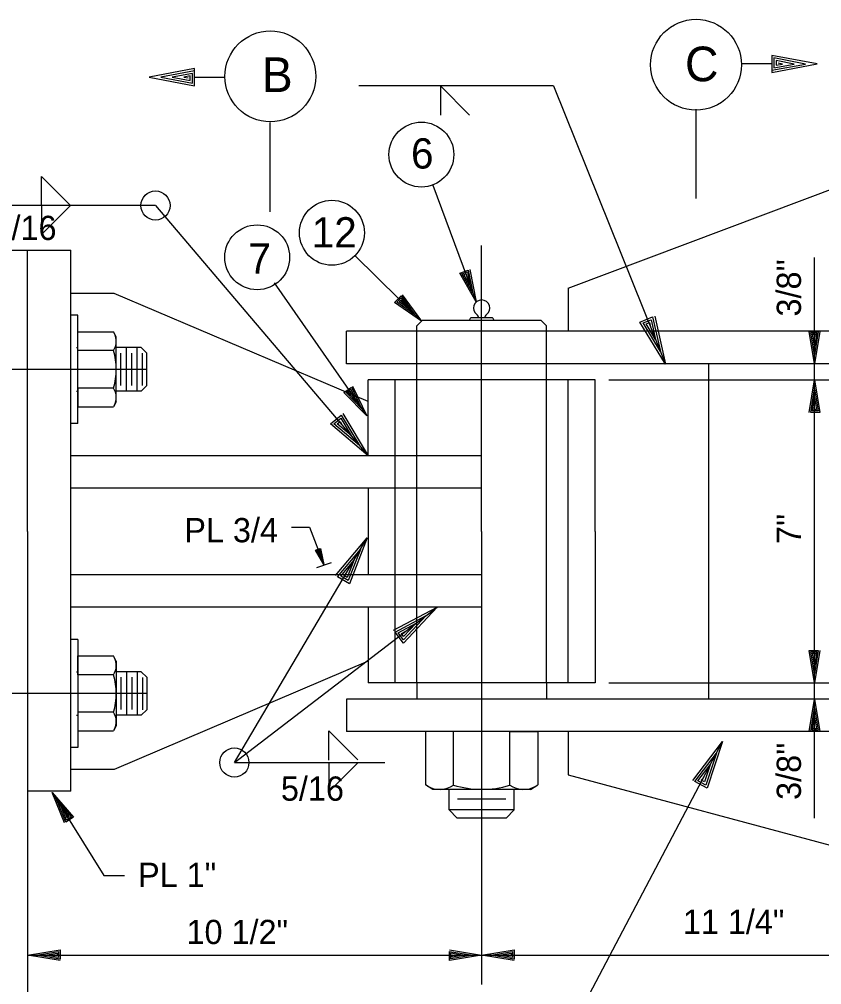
# Model space of a CAD drawing. Extents: x 0.1 to 13.5, y 0.1 to 9.5.
# Drawn here: x 2.665 to 4.211, y 1.527 to 3.386 of the extents above; entities that cross this region are included whole.
import ezdxf

# ---------------------------------------------------------------- set-up
doc = ezdxf.new("R2010")
doc.units = 0
for name, color, linetype in [('Level 2', 7, 'Continuous'), ('Level 25', 7, 'Continuous'), ('Level 3', 7, 'Continuous'), ('Level 4', 7, 'Continuous'), ('Level 50', 7, 'Continuous')]:
    doc.layers.add(name, color=color, linetype=linetype)

msp = doc.modelspace()

# ---------------------------------------------------------------- linework, layer by layer
at = {"layer": 'Level 2'}
for p, q in [((2.681, 2.3997), (2.681, 2.9413)), ((2.7644, 1.8997), (2.7644, 2.9413)), ((3.556, 2.3997), (3.556, 2.9502)), ((3.7227, 2.8684), (3.7227, 2.7851)), ((2.8477, 2.858), (2.7644, 2.858)), ((2.7777, 2.8159), (2.7646, 2.8159)), ((2.7777, 2.6076), (2.7777, 2.8159)), ((3.575, 2.8111), (3.537, 2.8111)), ((3.556, 2.8111), (3.556, 2.8111)), ((3.556, 2.8111), (3.556, 2.8111)), ((3.4415, 2.8059), (3.431, 2.7955)), ((3.431, 2.7851), (3.431, 2.7955)), ((3.6706, 2.8059), (3.4415, 2.8059)), ((3.5329, 2.8059), (3.5329, 2.8069)), ((3.5791, 2.8059), (3.5791, 2.8069)), ((3.6706, 2.8059), (3.681, 2.7955)), ((3.681, 2.7851), (3.681, 2.7955)), ((2.7777, 2.784), (2.8462, 2.784)), ((2.8518, 2.7743), (2.8462, 2.784)), ((2.8518, 2.6492), (2.8518, 2.7743)), ((4.306, 2.7851), (3.2956, 2.7851)), ((3.2956, 2.7226), (3.2956, 2.7851)), ((3.431, 2.7226), (3.431, 2.7851)), ((3.681, 2.7226), (3.681, 2.7851)), ((2.775, 2.7536), (2.7777, 2.7536)), ((2.9, 2.7536), (2.8518, 2.7536)), ((2.8714, 2.6699), (2.8714, 2.7536)), ((2.8923, 2.6699), (2.8923, 2.7536)), ((2.9, 2.7536), (2.9105, 2.7431)), ((2.8464, 2.7479), (2.7777, 2.7479)), ((2.8609, 2.6805), (2.8609, 2.7427)), ((2.8818, 2.6805), (2.8818, 2.7427)), ((2.9023, 2.681), (2.9023, 2.7432)), ((2.9105, 2.6804), (2.9105, 2.7431)), ((2.9105, 2.6804), (2.9105, 2.7431)), ((4.306, 2.7226), (3.2956, 2.7226)), ((3.431, 2.6913), (3.431, 2.7226)), ((3.681, 2.6913), (3.681, 2.7226)), ((3.9935, 2.0768), (3.9935, 2.7226)), ((2.9, 2.6699), (2.9105, 2.6804)), ((3.7748, 2.6913), (3.3373, 2.6913)), ((3.3373, 2.5455), (3.3373, 2.6913)), ((3.3894, 2.108), (3.3894, 2.6913)), ((3.431, 2.108), (3.431, 2.6913)), ((3.681, 2.108), (3.681, 2.6913)), ((3.7227, 2.108), (3.7227, 2.6913)), ((3.7748, 2.3997), (3.7748, 2.6913)), ((2.775, 2.6699), (2.7777, 2.6699)), ((2.7777, 2.6761), (2.7777, 2.6395)), ((2.8464, 2.6756), (2.7777, 2.6756)), ((2.9, 2.6699), (2.8518, 2.6699)), ((2.8518, 2.6492), (2.8462, 2.6395)), ((2.7777, 2.6395), (2.8462, 2.6395)), ((2.7777, 2.6076), (2.7646, 2.6076)), ((3.556, 2.5455), (2.7644, 2.5455)), ((3.556, 2.483), (3.556, 2.5455)), ((3.556, 2.483), (2.7644, 2.483)), ((3.3373, 2.483), (3.3373, 2.3163)), ((2.681, 2.3997), (2.681, 1.4864)), ((3.556, 2.3997), (3.556, 1.5274)), ((3.7748, 2.3997), (3.7748, 2.108)), ((3.556, 2.3163), (2.7644, 2.3163)), ((3.556, 2.3163), (3.556, 2.2538)), ((3.556, 2.2538), (2.7644, 2.2538)), ((3.3373, 2.2538), (3.3373, 2.108)), ((2.7777, 2.1917), (2.7646, 2.1917)), ((2.7777, 2.1917), (2.7777, 1.9834)), ((2.7777, 2.1232), (2.7777, 2.1598)), ((2.7777, 2.1598), (2.8462, 2.1598)), ((2.8518, 2.1501), (2.8462, 2.1598)), ((2.8518, 2.1501), (2.8518, 2.025)), ((2.775, 2.1294), (2.7777, 2.1294)), ((2.8464, 2.1238), (2.7777, 2.1238)), ((2.9, 2.1294), (2.8518, 2.1294)), ((2.8714, 2.1294), (2.8714, 2.0457)), ((2.8923, 2.1294), (2.8923, 2.0457)), ((2.9, 2.1294), (2.9105, 2.1189)), ((2.8609, 2.1188), (2.8609, 2.0566)), ((2.8818, 2.1188), (2.8818, 2.0566)), ((2.9023, 2.1183), (2.9023, 2.0561)), ((2.9105, 2.1189), (2.9105, 2.0562)), ((2.9105, 2.1189), (2.9105, 2.0562)), ((3.7748, 2.108), (3.3373, 2.108)), ((3.431, 2.108), (3.431, 2.0768)), ((3.681, 2.108), (3.681, 2.0768)), ((4.306, 2.0768), (3.2956, 2.0768)), ((3.2956, 2.0768), (3.2956, 2.0143)), ((2.775, 2.0457), (2.7777, 2.0457)), ((2.8464, 2.0514), (2.7777, 2.0514)), ((2.9, 2.0457), (2.8518, 2.0457)), ((2.9, 2.0457), (2.9105, 2.0562)), ((2.7777, 2.0154), (2.8462, 2.0154)), ((2.8518, 2.025), (2.8462, 2.0154)), ((4.306, 2.0143), (3.2956, 2.0143)), ((3.7123, 2.0143), (3.3998, 2.0143)), ((3.4477, 2.0143), (3.4477, 1.9114)), ((3.5018, 1.9112), (3.5018, 2.0143)), ((3.6095, 2.0143), (3.6644, 2.0143)), ((3.6103, 1.9112), (3.6103, 2.0143)), ((3.6644, 2.0143), (3.6644, 1.9114)), ((3.7227, 2.0143), (3.7227, 1.9309)), ((2.7777, 1.9834), (2.7646, 1.9834)), ((2.8477, 1.9413), (2.7644, 1.9413)), ((2.7644, 1.8997), (2.681, 1.8997)), ((3.4622, 1.903), (3.4477, 1.9114)), ((3.6499, 1.903), (3.4622, 1.903)), ((3.4933, 1.8633), (3.4933, 1.903)), ((3.6188, 1.8633), (3.6188, 1.903)), ((3.6499, 1.903), (3.6644, 1.9114)), ((3.6029, 1.8843), (3.5096, 1.8843)), ((3.4933, 1.8633), (3.509, 1.8476)), ((3.6188, 1.8633), (3.4933, 1.8633)), ((3.6188, 1.8633), (3.6031, 1.8476)), ((3.6031, 1.8476), (3.509, 1.8476)), ((3.6031, 1.8476), (3.509, 1.8476)), ((3.6029, 1.8476), (3.5096, 1.8476))]:
    msp.add_line(p, q, dxfattribs=at)
for centre, radius, start, end in [((3.556, 2.8298), 0.0156, 306.8699, 233.1301), ((3.537, 2.8069), 0.00417, 90, 180), ((3.5404, 2.8089), 0.0104, 11.771, 53.1301), ((3.5717, 2.8089), 0.0104, 126.8699, 168.229), ((3.575, 2.8069), 0.00417, 0, 90), ((2.8205, 2.7657), 0.0314, 325.489, 30.2876), ((2.7264, 2.7113), 0.1255, 343.5034, 16.9816), ((2.8205, 2.6578), 0.0314, 329.7124, 34.511), ((2.8205, 2.1415), 0.0314, 325.489, 30.2876), ((2.7264, 2.088), 0.1255, 343.0184, 16.4966), ((2.8205, 2.0336), 0.0314, 329.7124, 34.511), ((3.4751, 1.9499), 0.047, 239.7124, 304.511), ((3.5567, 2.0912), 0.1882, 253.0184, 286.4966), ((3.6369, 1.9499), 0.047, 235.489, 300.2876)]:
    msp.add_arc(centre, radius, start, end, dxfattribs=at)
at = {"layer": 'Level 25'}
for p, q in [((3.7227, 2.8684), (4.306, 3.0872)), ((2.5977, 2.9413), (2.681, 2.9413)), ((2.681, 2.9413), (2.7644, 2.9413)), ((3.3373, 2.6497), (2.8477, 2.858)), ((3.9004, 2.7461), (3.9004, 2.7461)), ((3.9101, 2.7219), (3.9101, 2.7219)), ((2.7644, 2.6497), (2.7644, 2.6497)), ((3.3204, 2.5653), (3.3204, 2.5653)), ((3.3373, 2.5455), (3.3373, 2.5455)), ((3.3355, 2.3873), (3.3355, 2.3873)), ((3.3222, 2.3649), (3.3222, 2.3649)), ((3.0794, 1.9546), (3.47, 2.2538)), ((3.47, 2.2538), (3.47, 2.2538)), ((3.4493, 2.238), (3.4493, 2.238)), ((3.3373, 2.1497), (2.8477, 1.9413)), ((3.7141, 1.4148), (4.0204, 1.9954)), ((4.0204, 1.9954), (4.0204, 1.9954)), ((4.0083, 1.9724), (4.0083, 1.9724)), ((3.7227, 1.9309), (4.306, 1.7747))]:
    msp.add_line(p, q, dxfattribs=at)
for points in [[(3.8896, 2.8145), (3.9101, 2.7219), (3.8608, 2.8029), (3.8854, 2.8128), (3.9004, 2.7461), (3.867, 2.8011), (3.8828, 2.8074), (3.8911, 2.7693), (3.8731, 2.7992), (3.8796, 2.8018), (3.8814, 2.7934)], [(3.2885, 2.6268), (3.3373, 2.5455), (3.2649, 2.6067), (3.2851, 2.6238), (3.3204, 2.5653), (3.2713, 2.6069), (3.2843, 2.6179), (3.3042, 2.5843), (3.2777, 2.6071), (3.283, 2.6116), (3.2874, 2.6041)], [(3.2745, 2.3148), (3.3355, 2.3873), (3.3012, 2.299), (3.2784, 2.3125), (3.3222, 2.3649), (3.2989, 2.305), (3.2843, 2.3136), (3.3095, 2.3434), (3.2966, 2.3109), (3.2906, 2.3145), (3.2962, 2.3211)], [(3.3863, 2.2093), (3.47, 2.2538), (3.4052, 2.1847), (3.3891, 2.2057), (3.4493, 2.238), (3.4053, 2.1911), (3.395, 2.2046), (3.4295, 2.2228), (3.4055, 2.1975), (3.4012, 2.203), (3.4089, 2.207)], [(3.9631, 1.9199), (4.0204, 1.9954), (3.9905, 1.9054), (3.967, 1.9178), (4.0083, 1.9724), (3.9879, 1.9113), (3.9729, 1.9193), (3.9966, 1.9503), (3.9854, 1.9172), (3.9792, 1.9204), (3.9845, 1.9273)]]:
    msp.add_lwpolyline(points, dxfattribs=at)
at = {"layer": 'Level 3'}
for p, q in [((4.115, 3.3001), (4.0566, 3.3001)), ((3.0028, 3.2743), (3.0611, 3.2743)), ((3.6946, 3.2576), (3.9101, 2.7219)), ((3.9691, 3.0406), (3.9691, 3.2127)), ((3.1486, 3.0149), (3.1486, 3.187)), ((3.4616, 3.0668), (3.5452, 2.8421)), ((2.9274, 3.0273), (3.3373, 2.5455)), ((3.3119, 2.9308), (3.4398, 2.8043)), ((4.1974, 2.7226), (4.1974, 2.9269)), ((3.1563, 2.8782), (3.3345, 2.6223)), ((3.5391, 2.8583), (3.5391, 2.8583)), ((3.5452, 2.8421), (3.5452, 2.8421)), ((3.4275, 2.8165), (3.4275, 2.8165)), ((3.4398, 2.8043), (3.4398, 2.8043)), ((4.1974, 2.7399), (4.1974, 2.7399)), ((4.1974, 2.6913), (4.1974, 2.7372)), ((4.1974, 2.7226), (4.1974, 2.7226)), ((2.9105, 2.7118), (2.0097, 2.7118)), ((3.8011, 2.6913), (4.2471, 2.6913)), ((4.1974, 2.108), (4.1974, 2.6913)), ((4.1974, 2.6913), (4.1974, 2.6913)), ((4.1974, 2.674), (4.1974, 2.674)), ((3.3246, 2.6365), (3.3246, 2.6365)), ((3.3345, 2.6223), (3.3345, 2.6223)), ((3.1896, 2.4078), (3.2239, 2.4078)), ((3.2239, 2.4078), (3.252, 2.3362)), ((3.0794, 1.9546), (3.3355, 2.3873)), ((3.2488, 2.3442), (3.2488, 2.3442)), ((3.2383, 2.3304), (3.2664, 2.3398)), ((3.252, 2.3362), (3.252, 2.3362)), ((4.1974, 2.1253), (4.1974, 2.1253)), ((3.8011, 2.108), (4.2668, 2.108)), ((4.1974, 2.0768), (4.1974, 2.108)), ((4.1974, 2.108), (4.1974, 2.108)), ((2.9105, 2.0876), (2.0065, 2.0876)), ((4.1974, 1.8477), (4.1974, 2.0768)), ((4.1974, 2.0768), (4.1974, 2.0768)), ((4.1974, 2.0594), (4.1974, 2.0594)), ((3.0794, 1.9546), (3.3692, 1.9546)), ((2.728, 1.8968), (2.8278, 1.7369)), ((2.728, 1.8968), (2.728, 1.8968)), ((2.7371, 1.8821), (2.7371, 1.8821)), ((2.8278, 1.7369), (2.8675, 1.7369)), ((2.681, 1.5835), (2.681, 1.5835)), ((2.681, 1.5835), (3.556, 1.5835)), ((2.6984, 1.5835), (2.6984, 1.5835)), ((3.5387, 1.5835), (3.5387, 1.5835)), ((3.556, 1.5835), (3.556, 1.5835)), ((3.556, 1.5835), (4.4935, 1.5835))]:
    msp.add_line(p, q, dxfattribs=at)
for points in [[(4.115, 3.2878), (4.115, 3.2835), (4.2025, 3.3001), (4.115, 3.3164), (4.115, 3.2878), (4.1801, 3.2998), (4.1192, 3.3115), (4.1192, 3.2926), (4.1581, 3.2998), (4.1233, 3.3063), (4.1233, 3.2976), (4.1358, 3.2998), (4.1275, 3.3014)], [(3.0028, 3.2866), (3.0028, 3.291), (2.9153, 3.2743), (3.0028, 3.258), (3.0028, 3.2866), (2.9376, 3.2746), (2.9986, 3.263), (2.9986, 3.2818), (2.9596, 3.2746), (2.9945, 3.2681), (2.9945, 3.2768), (2.982, 3.2746), (2.9903, 3.273)], [(3.5331, 2.9041), (3.5452, 2.8421), (3.5138, 2.8969), (3.5303, 2.9031), (3.5391, 2.8583), (3.5178, 2.8956), (3.5284, 2.8995), (3.5333, 2.8739), (3.5219, 2.8942), (3.5262, 2.8958), (3.5273, 2.8902)], [(3.4028, 2.8555), (3.4398, 2.8043), (3.3883, 2.8408), (3.4007, 2.8533), (3.4275, 2.8165), (3.3925, 2.8413), (3.4005, 2.8493), (3.4157, 2.8282), (3.3967, 2.8418), (3.4, 2.8451), (3.4033, 2.8404)], [(4.2078, 2.7849), (4.1974, 2.7226), (4.1871, 2.7849), (4.2048, 2.7849), (4.1974, 2.7399), (4.1904, 2.7823), (4.2018, 2.7823), (4.1974, 2.7566), (4.1938, 2.7796), (4.1984, 2.7796), (4.1974, 2.7739)], [(3.3074, 2.6793), (3.3345, 2.6223), (3.2904, 2.6675), (3.3049, 2.6776), (3.3246, 2.6365), (3.2947, 2.6672), (3.304, 2.6737), (3.3151, 2.6502), (3.2989, 2.6669), (3.3028, 2.6696), (3.3052, 2.6644)], [(4.1871, 2.629), (4.1974, 2.6913), (4.2078, 2.629), (4.1901, 2.629), (4.1974, 2.674), (4.2044, 2.6317), (4.1931, 2.6317), (4.1974, 2.6573), (4.2011, 2.6343), (4.1964, 2.6343), (4.1974, 2.64)], [(3.2454, 2.3671), (3.252, 2.3362), (3.2358, 2.3633), (3.244, 2.3665), (3.2488, 2.3442), (3.2378, 2.3627), (3.2431, 2.3647), (3.2458, 2.352), (3.2399, 2.362), (3.2421, 2.3629), (3.2426, 2.3601)], [(4.2078, 2.1703), (4.1974, 2.108), (4.1871, 2.1703), (4.2048, 2.1703), (4.1974, 2.1253), (4.1904, 2.1677), (4.2018, 2.1677), (4.1974, 2.142), (4.1938, 2.165), (4.1984, 2.165), (4.1974, 2.1593)], [(4.1871, 2.0144), (4.1974, 2.0768), (4.2078, 2.0144), (4.1901, 2.0144), (4.1974, 2.0594), (4.2044, 2.0171), (4.1931, 2.0171), (4.1974, 2.0428), (4.2011, 2.0198), (4.1964, 2.0198), (4.1974, 2.0254)], [(2.7522, 1.8384), (2.728, 1.8968), (2.7697, 1.8494), (2.7548, 1.84), (2.7371, 1.8821), (2.7655, 1.8499), (2.7559, 1.8439), (2.746, 1.8679), (2.7613, 1.8504), (2.7573, 1.8479), (2.7551, 1.8532)], [(2.7434, 1.5732), (2.681, 1.5835), (2.7434, 1.5939), (2.7434, 1.5762), (2.6984, 1.5835), (2.7407, 1.5905), (2.7407, 1.5792), (2.715, 1.5835), (2.738, 1.5872), (2.738, 1.5825), (2.7324, 1.5835)], [(3.4937, 1.5939), (3.556, 1.5835), (3.4937, 1.5732), (3.4937, 1.5909), (3.5387, 1.5835), (3.4964, 1.5765), (3.4964, 1.5879), (3.522, 1.5835), (3.499, 1.5799), (3.499, 1.5845), (3.5047, 1.5835)]]:
    msp.add_lwpolyline(points, dxfattribs=at)
for centre, radius in [((3.9691, 3.2984), 0.0875), ((3.1487, 3.276), 0.0875), ((3.4398, 3.1254), 0.0625), ((3.2674, 2.9748), 0.0625), ((3.1234, 2.9276), 0.0625)]:
    msp.add_circle(centre, radius, dxfattribs=at)
at = {"layer": 'Level 4'}
for p, q in [((3.6946, 3.2576), (3.3195, 3.2576)), ((3.4767, 3.2576), (3.4767, 3.2014)), ((3.4767, 3.2576), (3.5327, 3.2016)), ((2.7077, 3.083), (2.7636, 3.0271)), ((2.7077, 3.0267), (2.7077, 3.083)), ((2.9274, 3.0273), (2.5523, 3.0273)), ((2.7077, 3.0279), (2.7077, 2.9716)), ((2.7077, 2.9716), (2.7636, 3.0275)), ((3.2612, 2.0154), (3.3171, 1.9596)), ((3.2612, 1.9592), (3.2612, 2.0154)), ((3.2612, 1.9546), (3.2612, 1.8984)), ((3.2612, 1.8984), (3.3171, 1.9543))]:
    msp.add_line(p, q, dxfattribs=at)
for centre in [(2.9274, 3.0273), (3.0794, 1.9546)]:
    msp.add_circle(centre, 0.0281, dxfattribs=at)
at = {"layer": 'Level 50'}
for p, q in [((3.556, 1.5835), (3.556, 1.5835)), ((3.556, 1.5835), (3.556, 1.5835)), ((3.5604, 1.5835), (3.5604, 1.5835)), ((3.5734, 1.5835), (3.5734, 1.5835))]:
    msp.add_line(p, q, dxfattribs=at)
for points in [[(3.6184, 1.5732), (3.556, 1.5835), (3.6184, 1.5939), (3.6184, 1.5762), (3.5734, 1.5835), (3.6157, 1.5905), (3.6157, 1.5792), (3.59, 1.5835), (3.613, 1.5872), (3.613, 1.5825), (3.6074, 1.5835)], [(3.5716, 1.5809), (3.556, 1.5835), (3.5716, 1.5861), (3.5716, 1.5817), (3.5604, 1.5835), (3.571, 1.5853), (3.571, 1.5824), (3.5645, 1.5835), (3.5703, 1.5844), (3.5703, 1.5833), (3.5689, 1.5835)]]:
    msp.add_lwpolyline(points, dxfattribs=at)

# ---------------------------------------------------------------- texts
at = {"layer": 'Level 3'}
for s, height, p in [('C', 0.0667, (3.9479, 3.2666)), ('B', 0.0667, (3.1323, 3.2459)), ('6', 0.0583, (3.4198, 3.0985)), ('5/16', 0.04667, (2.6152, 2.9609)), ('12', 0.05833, (3.2285, 2.9465)), ('7', 0.0583, (3.1065, 2.8962)), ('PL 3/4', 0.04667, (2.983, 2.3788)), ('5/16', 0.04667, (3.1691, 1.8811)), ('PL 1"', 0.04667, (2.8939, 1.715)), ('11 1/4"', 0.04667, (3.9437, 1.6247)), ('10 1/2"', 0.04667, (2.9872, 1.605))]:
    msp.add_text(s, height=height, dxfattribs=at).set_placement(p)
for s, p in [("3/8''", (4.1713, 2.8135)), ("7''", (4.1713, 2.3753)), ("3/8''", (4.1713, 1.8826))]:
    msp.add_text(s, height=0.04667, rotation=90, dxfattribs=at).set_placement(p)

doc.saveas('drawing.dxf')
